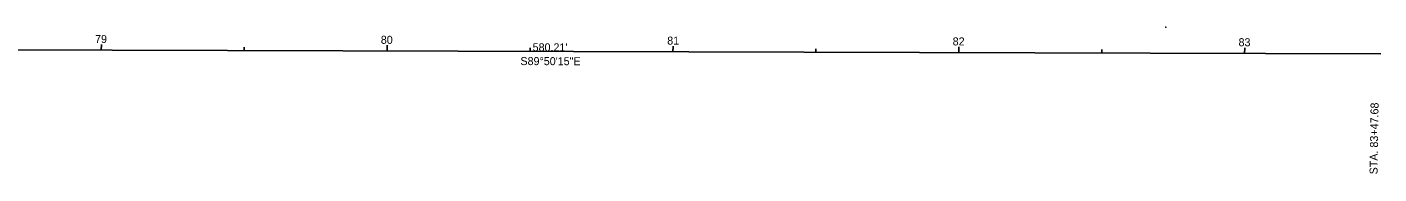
# Model space of a CAD drawing. Extents: x 2201792 to 2205434, y 633651 to 635766.
# Drawn here: x 2203623.7 to 2204096.7, y 635480.2 to 635531.4 of the extents above; entities that cross this region are included whole.
import ezdxf

# ---------------------------------------------------------------- set-up
doc = ezdxf.new("R2010")
doc.units = 0
for name, color, linetype in [('_CIVIL_CONSTRUCTION', 7, 'Continuous'), ('GE_P_Alignment', 7, 'Continuous'), ('GE_P_Alignment_100_Bearings', 7, 'Continuous'), ('GE_P_Alignment_100_Cardinal_Points', 7, 'Continuous'), ('GE_P_Alignment_100_Distances', 7, 'Continuous'), ('GE_P_Alignment_100_Stations', 7, 'Continuous')]:
    doc.layers.add(name, color=color, linetype=linetype)

msp = doc.modelspace()

# ---------------------------------------------------------------- linework, layer by layer
at = {"layer": '_CIVIL_CONSTRUCTION'}
msp.add_circle((2204022.07, 635531.39), 0.05, dxfattribs=at)
at = {"layer": 'GE_P_Alignment'}
msp.add_line((2203517.16, 635523.76), (2204097.36, 635522.11), dxfattribs=at)
msp.add_line((2203517.16, 635523.76), (2204097.36, 635522.11), dxfattribs=at)
at = {"layer": 'GE_P_Alignment_100_Stations'}
for p, q in [((2203649.68, 635523.38), (2203649.69, 635525.38)), ((2203749.68, 635523.1), (2203749.69, 635525.1)), ((2203699.68, 635523.24), (2203699.69, 635524.44)), ((2203799.68, 635522.96), (2203799.69, 635524.16)), ((2203849.68, 635522.81), (2203849.69, 635524.81)), ((2203899.68, 635522.67), (2203899.69, 635523.87)), ((2203949.68, 635522.53), (2203949.69, 635524.53)), ((2203999.68, 635522.39), (2203999.69, 635523.59)), ((2204049.68, 635522.25), (2204049.69, 635524.25))]:
    msp.add_line(p, q, dxfattribs=at)

# ---------------------------------------------------------------- texts
at = {"layer": 'GE_P_Alignment_100_Bearings'}
msp.add_text('S89°50\'15"E', height=2.8, rotation=359.8376, dxfattribs=at).set_placement((2203796.31, 635518.17))
at = {"layer": 'GE_P_Alignment_100_Cardinal_Points'}
msp.add_text(' STA. 83+47.68', height=2.8, rotation=89.136, dxfattribs=at).set_placement((2204096.15, 635478.94))
at = {"layer": 'GE_P_Alignment_100_Distances'}
msp.add_text("580.21'", height=2.8, rotation=359.8376, dxfattribs=at).set_placement((2203800.58, 635522.99))
at = {"layer": 'GE_P_Alignment_100_Stations'}
for s, p in [('79', (2203647.49, 635525.89)), ('80', (2203747.46, 635525.6)), ('81', (2203847.66, 635525.32)), ('82', (2203947.53, 635525.04)), ('83', (2204047.54, 635524.75))]:
    msp.add_text(s, height=2.8, rotation=359.8376, dxfattribs=at).set_placement(p)

doc.saveas('drawing.dxf')
